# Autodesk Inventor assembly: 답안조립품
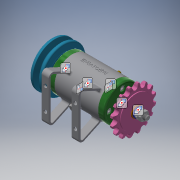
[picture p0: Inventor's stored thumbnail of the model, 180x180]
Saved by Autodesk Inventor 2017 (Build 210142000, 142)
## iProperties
Part Number: 답안조립품
Material: 일반
Document SubType Name: Assembly
Designer: Administrator
Author: Administrator
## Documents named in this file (16)
- C:\Users\Administrator\Desktop\711206V1024\답안조립품.iam
- C:\Users\Administrator\Desktop\711206V1024\본체.ipt
- C:\Users\Administrator\Desktop\711206V1024\축.ipt
- C:\Users\Administrator\Desktop\711206V1024\베어링 6002.ipt
- C:\Users\Administrator\Desktop\711206V1024\커버.ipt
- C:\Users\Administrator\Desktop\711206V1024\볼트 M4 x 12.ipt
- C:\Users\Administrator\Desktop\711206V1024\오일 실 15 x 25 x 7.ipt
- C:\Users\Administrator\Desktop\711206V1024\스프로킷.ipt
- C:\Users\Administrator\Desktop\711206V1024\V벨트풀리.ipt
- C:\Users\Administrator\Desktop\711206V1024\키 3 x 3.ipt
- C:\Users\Administrator\Desktop\711206V1024\와셔 8 x 17.ipt
- C:\Users\Administrator\Desktop\711206V1024\스프링와셔 8.ipt
- C:\Users\Administrator\Desktop\711206V1024\너트 M8.ipt
- C:\Users\Administrator\Desktop\711206V1024\와셔 6 x 11.5.ipt
- C:\Users\Administrator\Desktop\711206V1024\볼트 M6 x 8.ipt
- C:\Users\Administrator\Desktop\711206V1024\니플 M6 x 0.75.ipt
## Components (11 placed, 3 different names)
1. KS B 2023 6002 - 15 x 32 x 9:1
2. KS B 2023 6002 - 15 x 32 x 9:2
3. V벨트풀리:1
4. ISO 4762 M4 x 12:1
5. ISO 4762 M4 x 12:3
6. ISO 4762 M4 x 12:4
7. ISO 4762 M4 x 12:5
8. ISO 4762 M4 x 12:2
9. ISO 4762 M4 x 12:6
10. ISO 4762 M4 x 12:7
11. ISO 4762 M4 x 12:8
